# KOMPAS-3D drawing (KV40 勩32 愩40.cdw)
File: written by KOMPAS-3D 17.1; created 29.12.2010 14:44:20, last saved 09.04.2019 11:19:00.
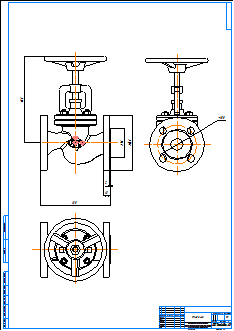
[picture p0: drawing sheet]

Title block, sheet 1: name: KV 40 Ду32; material: Внимание! Данный продукт является объектом авторского права ООО «Торговый Дом АДЛ». / Запрещается изменение, копирование, распространение / (в том числе путем копирования на другие сайты и ресурсы в Интернете) / или любое иное использование информации и объектов без предварительного / согласия правообладателя (ООО «Торговый Дом АДЛ»).; scale: 1:1; sheets: 1; organisation: ООО "Торговый дом АДЛ"; sheet format: A1; stored path: \\adlc.lan\data\АДЛ_ПКД\3D-модели\ADL production\Вентили ГРАНВЕНТ\KV40\KOMPAS 2D\KV 40 Ду32.cdw

Views: Спереди 1, Проекционный вид 2, Проекционный вид 3
Dimensions and other numbers on the sheet: 78; 140; 2; 18; 180; 220; 100; 1:1; 1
